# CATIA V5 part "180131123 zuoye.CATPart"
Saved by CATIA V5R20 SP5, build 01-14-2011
Part number: 作业
Bounding box of the stored display mesh (mm): x -56.792 to 87.381, y -88.746 to 98.689, z -110.871 to 69.804
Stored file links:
  E:\180131123\180131123 zuoye.CATPart
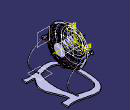
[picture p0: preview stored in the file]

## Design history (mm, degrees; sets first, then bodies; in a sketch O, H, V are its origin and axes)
Body1 (main body)
  Sketch1 on yz-plane, origin (0, 0, 0), H (0, 1, 0), V (0, 0, 1)
    circle A1 centre (0, 0) radius 70
    circle A2 centre (0, 0) radius 63
    radius A1 = 70
    distance A2 A1 = 7
  Pad1: profile Sketch1, direction (1, 0, 0), length 1
  Plane1: type Offset, RefPlane yz-plane, Offset 30, reversed
  Sketch2 on Plane1, origin (-30, 0, 0), H (0, 1, 0), V (0, 0, 1)
    circle A1 centre (0, 0) radius 22
    radius A1 = 22
  Pad2: profile Sketch2, direction (1, 0, 0), length 2.5
  Sketch3 on xy-plane, origin (0, 0, 0), H (1, 0, 0), V (0, 1, 0)
    spline S1 through (0, 66.3104) (-16.3503, 63.8085) (-25.5791, 54.2044) (-29.5458, 34.9961) (-30.0315, 21.8408) (-27.522, 21.8408)
    spline S2 through (0, 59.6925) (-16.3503, 56.3028) (-22.0171, 43.1475) (-27.522, 21.8408)
    line L1 (0, 66.3104) -> (0, 59.6925)
    point P1 (0, 66.3104)
    point P2 (0, 59.6925)
    point P3 (0, 66.3104)
    point P4 (-27.522, 21.8408)
    point P5 (0, 59.6925)
    point P6 (-27.522, 21.8408)
    coincidence: P3 V, P5 V, P6 P4, P3 P1, P5 P2
    vertical: L1 V
  Pad3: profile Sketch3, direction (0, 0, 1), length 0.6
  CircPattern1: of Pad3, instances 8, angular step 45, axis from start face of Pad1
  Sketch4 on xy-plane, origin (0, 0, 0), H (1, 0, 0), V (0, 1, 0)
  Sketch5 on face of CircPattern1, origin (0, 0, 0), H (-1, 0, 0), V (0, 0.7071, 0.7071)
  Sketch6 on face of CircPattern1, origin (0, 0, 0), H (-1, 0, 0), V (0, 0.7071, 0.7071)
  Plane2: type Offset, RefPlane yz-plane, Offset 8, reversed
  Plane3: type Offset, RefPlane yz-plane, Offset 15, reversed
  Plane4: type Offset, RefPlane yz-plane, Offset 20, reversed
  Plane5: type Offset, RefPlane yz-plane, Offset 23, reversed
  Plane6: type Offset, RefPlane yz-plane, Offset 25, reversed
  Plane7: type Offset, RefPlane yz-plane, Offset 28, reversed
  Sketch7 on face of CircPattern1, origin (0, 0, 0), H (-1, 0, 0), V (0, 0, 1)
    point P1 (8, 63)
    point P2 (15, 60)
    point P3 (20, 54)
    point P4 (23, 47)
    point P5 (25, 40)
    point P6 (28, 28)
    distance P1 V = 8
    distance P1 H = 63
    distance P2 V = 15
    distance P2 H = 60
    distance P3 V = 20
    distance P3 H = 54
    distance P4 V = 23
    distance P4 H = 47
    distance P5 V = 25
    distance P5 H = 40
    distance P6 V = 28
    distance P6 H = 28
  Sketch8 on Plane2, origin (-8, 0, 0), H (0, 1, 0), V (0, 0, 1)
    circle A1 centre (0, 0) radius 63
    radius A1 = 63
  Sketch9 on Plane3, origin (-15, 0, 0), H (0, 1, 0), V (0, 0, 1)
    circle A1 centre (0, 0) radius 60
    radius A1 = 60
  Sketch10 on Plane4, origin (-20, 0, 0), H (0, 1, 0), V (0, 0, 1)
    circle A1 centre (0, 0) radius 54
    radius A1 = 54
  Sketch11 on Plane5, origin (-23, 0, 0), H (0, 1, 0), V (0, 0, 1)
    circle A1 centre (0, 0) radius 47
    radius A1 = 47
  Sketch12 on Plane6, origin (-25, 0, 0), H (0, 1, 0), V (0, 0, 1)
    circle A1 centre (0, 0) radius 40
    radius A1 = 40
  Sketch13 on Plane7, origin (-28, 0, 0), H (0, 1, 0), V (0, 0, 1)
    circle A1 centre (0, 0) radius 28
    radius A1 = 28
  Sketch14 on face of CircPattern1, origin (0, 0, 0), H (-1, 0, 0), V (0, 0, 1)
    circle A1 centre (8, 63) radius 0.6
    point P1 (8, 63)
    circle A2 centre (15, 60) radius 0.6
    point P2 (15, 60)
    distance P1 V = 8
    distance P1 H = 63
    radius A1 = 0.6
    distance P2 V = 15
    distance P2 H = 60
    radius A2 = 0.6
  Rib1: profile Sketch14, centre curve Sketch8
  Sketch15 on face of CircPattern1, origin (0, 0, 0), H (-1, 0, 0), V (0, 0, 1)
    circle A1 centre (20, 54) radius 0.6
    point P1 (20, 54)
    circle A2 centre (23, 47) radius 0.6
    point P2 (23, 47)
    circle A3 centre (25, 40) radius 0.6
    point P3 (25, 40)
    circle A4 centre (28, 28) radius 0.6
    point P4 (28, 28)
    distance P1 V = 20
    distance P1 H = 54
    radius A1 = 0.6
    distance P2 V = 23
    distance P2 H = 47
    radius A2 = 0.6
    distance P3 V = 25
    distance P3 H = 40
    radius A3 = 0.6
    distance P4 V = 28
    distance P4 H = 28
    radius A4 = 0.6
  Rib2: profile Sketch15, centre curve Sketch10
  Sketch16 on end face of Pad2, origin (-27.5, 0, 0), H (0, 1, 0), V (0, 0, 1)
    circle A1 centre (0, 0) radius 15
    circle A2 centre (0, 0) radius 13
    radius A1 = 15
    radius A2 = 13
  Pad4: profile Sketch16, direction (1, 0, 0), length 30
  Sketch17 on yz-plane, origin (0, 0, 0), H (0, 1, 0), V (0, 0, 1)
    line L1 (69.1227, -4.3923) -> (66.1227, -4.3923)
    line L2 (66.1227, -4.3923) -> (66.1227, 5.6077)
    line L3 (66.1227, 5.6077) -> (69.1227, 5.6077)
    line L4 (69.1227, 5.6077) -> (69.1227, -4.3923)
    length L4 = 10
    length L1 = 3
    horizontal: L1 H, L3 H
    vertical: L2 V, L4 V
  Pad5: profile Sketch17, direction (-1, 0, 0), length 20
  Sketch18 on face of Pad5 from Sketch17.L4, origin (0, 69.1227, 0), H (-1, 0, 0), V (0, 0, 1)
    line L1 (15.7198, 5.6065) -> (20.0533, 5.6065)
    arc A1 centre (21.198, 0.7144) radius 5.0242 from (20.0533, 5.6065) to (20.0533, -4.1777) cw
    point P4 (26.1711, 0)
    line L2 (20.0533, -4.1777) -> (14.7001, -4.1777)
    line L3 (14.7001, -4.1777) -> (14.7001, 5.6065)
    point P7 (14.7001, 5.6065)
    horizontal: L1 H, L2 H
    coincidence: A1 P4, P4 H, P7 L1
    vertical: L3 V
  Pad6: profile Sketch18, direction (0, -1, 0), length 3
  Sketch19 on face of Pad6, origin (0, 69.1227, 0), H (-1, 0, 0), V (0, 0, 1)
    circle A1 centre (18.2688, 0) radius 2.941
    point P1 (18.2688, 0)
    coincidence: P1 H
  Pad7: profile Sketch19, direction (0, 1, 0), length 6
  Mirror1: of Pad5, about zx-plane
  Mirror2: of Pad6, about zx-plane
  Mirror3: of Pad7, about zx-plane
  Mirror4: of the body so far, about yz-plane
  Plane8: type Offset, RefPlane face of Mirror4, Offset 2.25
  Sketch20 on Plane8, origin (0, -72.8727, 0), H (-1, 0, 0), V (0, 0, 1)
    spline S1 through (-17.8067, 0) (-73.0258, -49.2091) (-29.2258, -110.8714)
    point P1 (-17.8067, 0)
    coincidence: P1 H
  Plane9: type Offset, RefPlane xy-plane, Offset 2.25
  Plane10: type Equation, A 0, B 0, C 1, Length 20, RefPoint vertex of Sketch20
  Sketch21 on Plane10, origin (0, 0, -110.8714), H (1, 0, 0), V (0, 1, 0)
    circle A1 centre (29.2462, -72.8133) radius 2
    radius A1 = 2
  Rib3: profile Sketch21, centre curve Sketch20
  Mirror5: of Rib3, Sketch20, about zx-plane
  Sketch22 on Plane10, origin (0, 0, -110.8714), H (1, 0, 0), V (0, 1, 0)
    spline S1 through (87.381, -81.5811) (32.256, -81.5811) (-33.4699, -79.1151) (-47.2512, -56.921) (-51.4916, -41.7727) (-54.6718, -23.806) (-56.792, 2.6156) (-54.6718, 33.6168) (-51.4916, 57.9247) (-47.2512, 69.9025) (-33.4699, 89.6305) (34.7296, 89.6305) (87.381, 89.6305)
    point P1 (87.381, 89.6305)
    line L1 (87.381, 89.6305) -> (87.381, 64.9704)
    line L2 (87.381, 64.9704) -> (56.9916, 64.9704)
    point P3 (56.9916, 64.9704)
    spline S2 through (56.9916, 64.9704) (64.4122, 37.492) (77.1334, 8.9567) (79.2536, -29.7949) (64.4122, -55.1596) (56.9916, -64.3191)
    line L3 (56.9916, -64.3191) -> (87.381, -64.3191)
    point P4 (87.381, -64.3191)
    line L4 (87.381, -64.3191) -> (87.381, -81.5811)
    point P5 (87.381, -81.5811)
    point P6 (56.9916, -64.3191)
    spline S3 through (34.7296, 64.9704) (44.0581, 37.492) (47.247, -18.9631) (34.7296, -64.3191)
    spline S4 through (34.7296, 64.9704) (-33.4699, 64.9704) (-42.3962, 17.7739) (-33.4699, -60.2921) (34.7296, -64.3191)
    point P7 (56.9916, 64.9704)
    point P8 (87.381, -81.5811)
    point P9 (56.9916, -64.3191)
    point P10 (34.7296, 64.9704)
    point P11 (34.7296, -64.3191)
    point P12 (34.7296, 64.9704)
    point P13 (-33.4699, 64.9704)
    point P14 (34.7296, -64.3191)
    point P15 (87.381, 89.6305)
    coincidence: P1 S1, P7 P3, P4 L1, P8 P5, P9 P6, P10 L2, P11 L3, P12 P10, P13 L2, P14 P11, P15 P1
    vertical: L1 V, L4 V
    horizontal: L2 H, L3 H
  Pad8: profile Sketch22, direction (0, 0, 1), length 4.5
